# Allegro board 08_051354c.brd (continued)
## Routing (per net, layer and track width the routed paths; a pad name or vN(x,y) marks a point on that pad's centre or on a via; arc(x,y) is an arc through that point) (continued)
UNNAMED_5_ADP5023_I567_AVIN: length 18.1
  L8_SIG w0.508: v1(13.97,3.05) 14.22,3.05 15.01,3.84 15.01,4.76 14.35,5.42 14.35,9.86 v2(16.56,12.06)
  BOTTOM w0.133: R97.1 v1(13.97,3.05) ; v2(16.56,12.06) 16.65,12.16 U3.12
  BOTTOM w0.254: v1(19.43,17.14) 19.21,16.92 U3.22
  BOTTOM w0.305: U3.17 16.34,14.91 16,15.24 ; U3.7 v2(20.87,12.16) ; U3.3 21.92,14.41 ; 16.06,14.41 U3.16
  vias: v2(15.49,14.61) v2(15.75,15.88) v2(22.43,17.9) v2(23.24,17.95)
UNNAMED_5_ADP5023_I567_FB1: length 4.7
  TOP w0.305: v1(17.57,10.92) 17.57,10.11 17.7,9.98 R30.1 R23.1
  BOTTOM w0.133: U3.11 18.21,11.55 v1(17.57,10.92)
UNNAMED_5_ADP5023_I567_FB2: length 7.6
  TOP w0.305: v1(20.16,8.58) 20.16,10 20.83,10.67 v1(20.83,11.23)
  BOTTOM w0.133: R21.1 R20.1 19.35,8.17 19.75,8.58 v1(20.16,8.58)
  BOTTOM w0.305: U3.8 19.71,11.58 20.06,11.23 v1(20.83,11.23)
UNNAMED_5_ADP5023_I567_FB3: length 6.6
  TOP w0.133: v1(17.45,17.14) 17.09,16.79 14.38,16.79 14.01,17.15 R19.1 R18.2
  BOTTOM w0.254: v1(17.45,17.14) 17.71,16.88 U3.19
UNNAMED_5_ADP5023_I567_MODE: length 13.7
  L8_SIG w0.203: v1(16.38,10.67) 15.11,9.4 15.11,5.59 v1(17.65,3.05)
  BOTTOM w0.133: R97.2 v1(17.65,3.05) ; v1(16.38,10.67) 15.88,11.18 15.88,12.4 16.38,12.91 U3.13
UNNAMED_5_ADP5023_I567_SW1: length 4.5
  BOTTOM w0.254: U3.15 15.81,13.91 15.75,13.97 15.24,13.97 15.15,13.97 15.1,13.92 12.53,13.92
UNNAMED_5_ADP5023_I567_SW2: length 3.6
  BOTTOM w0.254: U3.4 24.57,13.91
UNNAMED_5_ADP5023_I567_VOUT1: length 9.4
  TOP w0.508: R22.1 20.06,7.4 18.95,8.51 v1(18.63,8.51) 18.02,7.91 R30.2
  BOTTOM w0.254: 18.71,10.83 U3.10 ; 18.71,10.83 18.72,10.84 ; 18.71,10.83 18.41,10.54
UNNAMED_5_ADP5023_I567_VOUT2: length 12.7
  BOTTOM w0.305: U3.9 19.21,10.05 19.6,9.65 ; 26.44,10.18 26.44,10.27 C47.1 26.5,10.25 26.44,10.18 ; 26.44,10.18 26.44,9.14 26.14,8.84 23.83,8.84 21.47,6.48 R21.2 20.49,5.34 R32.1
UNNAMED_5_ADP5023_I567_VOUT3: length 1.2
  BOTTOM w0.254: U3.20 18.21,17.35
  vias: v1(17.11,17.97) v1(17.79,17.97)
UNNAMED_5_ADP5071_I420_COMP1: length 2.1
  TOP w0.133: R50.1 26.67,24.51 25.89,23.73 U10.6
UNNAMED_5_ADP5071_I420_COMP2: length 1.9
  TOP w0.133: R51.1 23.29,24.61 23.89,24 U10.10
UNNAMED_5_ADP5071_I420_EN1: length 15.1
  TOP w0.133: R92.1 33.27,25.65 30.73,25.65 28.96,27.43 26.92,27.43 26.4,27.95 25.57,27.95 25.02,27.41 25.02,24.77 25.39,24.39 U10.7
UNNAMED_5_ADP5071_I420_EN2: length 20.8
  TOP w0.133: R85.2 36.83,25.26 36.83,26.54 36.32,27.05 33.07,27.05 30.78,29.34 27.12,29.34 26.53,28.75 25.45,28.75 24.39,27.69 U10.9
UNNAMED_5_ADP5071_I420_FB1: length 4.6
  TOP w0.133: 29.89,23.38 29.88,23.39 28.69,23.39 27.6,22.31 U10.5 ; 29.89,23.38 R48.1 ; 29.89,23.38 R52.1
UNNAMED_5_ADP5071_I420_FB2: length 6.2
  TOP w0.305: R49.1 R46.2 20.23,24.9 21.13,24.01 21.13,22.73 21.55,22.31 U10.11
UNNAMED_5_ADP5071_I420_INBK: length 4.4
  TOP w0.305: U10.1 30.28,20.31 30.84,20.87 L9.1
UNNAMED_5_ADP5071_I420_PVIN1: length 10.8
  TOP w0.305: U10.15 22.71,20.31 22.7,20.31 21.91,20.31 20.42,18.82 20.42,16.89 20.68,16.64 21.21,16.64 ; U10.16 23.89,16.24 C41.1 ; U10.17 24.39,18.04
UNNAMED_5_ADP5071_I420_SW2: length 1.5
  TOP w0.305: U10.18 24.89,17.83
UNNAMED_5_ADP5071_I420_VREF: length 6.3
  TOP w0.305: U10.12 21.12,21.81 20.29,22.63 C43.1 20.15,24.07 19.23,24.99 R46.1
UNNAMED_5_ADP5071_I420_VREG: length 3
  TOP w0.305: U10.14 21.14,20.81 20.37,20.04 C66.1
UNNAMED_5_ADP7112_I458_EN: length 8.7
  TOP w0.133: U12.C1 102.12,10.61 v1(102.12,11.18) 102.12,13.35 102.36,13.59 105.16,13.59 105.66,14.09 R111.2
  BOTTOM w0.133: v1(102.12,11.18) 102.13,11.18 R38.1
UNNAMED_5_ADP7112_I458_SENSE: length 5.4
  TOP w0.133: 100.98,10.24 101.18,10.03 U12.B2
  TOP w0.305: R57.1 97.51,9.84 R58.1 97.97,10.29 100.93,10.29 100.98,10.24
UNNAMED_5_ADP7112_I458_SS: length 2.7
  TOP w0.133: v1(103.52,10.41) 102.88,10.41 102.5,10.03 U12.B1
  BOTTOM w0.133: C80.1 103.78,10.68 v1(103.52,10.41)
UNNAMED_5_ADP7112_I458_VIN: length 4.1
  TOP w0.133: U12.A1 102.38,9.2
  TOP w0.508: R56.2 106.06,8.09 ; 104.03,7.73 C79.1 102.67,8.89
UNNAMED_5_ADP7112_I458_VOUT: length 6.1
  TOP w0.133: U12.A2 101.18,9.27
  TOP w0.508: R59.1 97.51,7.82 R58.2 97.58,8.89 C81.1 ; C81.1 99.45,7.75 ; C81.1 100.81,8.89
UNNAMED_5_CAP_I499_N1: length 20.8
  TOP w0.305: R49.2 19.23,27.55 v1(19.24,27.56)
  L3_SIG w0.305: v1(19.24,27.56) 19.24,25.56 20.24,24.57 20.24,9.57 21.05,8.76 v1(21.46,8.76)
UNNAMED_5_CAP_I500_N1: length 15.4
  TOP w0.133: R52.2 v1(31.77,23.37)
  TOP w0.508: C78.1 32.51,13.21 33.02,12.7 v1(33.02,11.69)
  L3_SIG w0.305: v1(31.77,23.37) 31.77,12.94 v1(33.02,11.69)
UNNAMED_5_CAP_I511_N1: length 16.4
  BOTTOM w0.508: 8.42,28.3 C42.1 ; C42.1 9.86,27.35 ; C42.1 11.29,28.3 ; C42.1 9.86,29.25 ; R100.2 8.07,32.14 ; R100.2 7.27,31.24 ; R100.2 7.27,33.04 ; E2.1 7.27,30.83 ; E2.1 7.27,28.57 ; E2.1 8.27,29.7 ; S2.2 14.15,26.54 ; S2.2 12.7,27.99 ; S2.2 11.25,26.54 ; S2.2 12.7,25.09
UNNAMED_5_CAP_I516_N1: length 1.1
  TOP w0.133: R50.2 C72.1
UNNAMED_5_CAP_I517_N1: length 1.1
  TOP w0.305: R51.2 C74.1
UNNAMED_5_CAP_I691_N1: length 2
  BOTTOM w0.279: U2.23 24.1,35.14 C38.1
UNNAMED_5_CAP_I700_N2: length 1.9
  BOTTOM w0.279: U2.28 26.6,35.01 C35.2
UNNAMED_5_CAP_I722_N2: length 1.4
  BOTTOM w0.254: R13.1 C91.2
UNNAMED_5_CN4PV6_I401_N1: length 21.8
  TOP w0.508: P31.1B 4.67,5.38 ; P31.1B 3.06,3.58 ; P31.1B 3.06,7.18 ; P31.1A 3.06,13.28 ; P31.1A 4.67,11.48 ; P31.1A 3.06,9.68 ; D1.C 7.23,19.11 ; D1.C 7.23,16.13 ; D1.C 5.94,17.62 ; D1.C 8.53,17.62 ; S2.1 14.15,21.84 ; S2.1 12.7,20.4 ; S2.1 12.7,23.29 ; S2.1 11.25,21.84
UNNAMED_5_DIOLED_I652_P: length 5.7
  TOP w0.508: DS1.A 7.64,34.66 v1(6.77,34.66)
  BOTTOM w0.508: v1(6.77,34.66) 5.57,33.46 R100.1
UNNAMED_5_DIOLED_I662_P: length 2.6
  TOP w0.508: v1(7.62,39.24) DS2.A
  BOTTOM w0.508: v1(7.62,39.24) R104.2
UNNAMED_5_DIOLED_I714_P: length 2.6
  TOP w0.508: DS3.A v1(7.61,42.42)
  BOTTOM w0.508: R108.1 v1(7.61,42.42)
UNNAMED_5_LINLTC3119_I686_RT: length 2.7
  BOTTOM w0.254: R14.1 22.73,26.8 24.1,28.16 U2.14
UNNAMED_5_LINLTC3119_I686_VC: length 2.1
  BOTTOM w0.254: U2.10 26.1,27.95 26.8,27.25 R13.2
UNNAMED_5_RES_I689_N2: length 1.6
  BOTTOM w0.133: R115.1 19.56,23.11 R15.2
UNNAMED_6_CAP_I286_N1: length 55.6
  TOP w0.305: v1(43.94,6.48) 43.18,5.71 C85.1 41.85,4.58 41.24,3.98 S4.1
  L8_SIG w0.203: v1(65.55,39.88) 65.55,39.39 64.52,38.35 56.31,38.35 51.94,33.99 51.94,21.44 50.25,19.75 48.2,19.75 44.52,16.07 44.52,14.36 44.55,14.34 44.55,7.08 v1(43.94,6.48)
  BOTTOM w0.133: P4.28 v1(65.55,39.88)
UNNAMED_6_CAP_I292_N1: length 66.2
  TOP w0.305: v1(36.96,5.71) C84.1 38.04,4.58 38.64,3.98 S3.2
  L8_SIG w0.203: v1(36.96,5.71) 36.96,6.73 37.92,7.7 42.27,7.7 43.18,6.78 43.18,6.32 43.79,5.71 44.32,5.71 45.06,6.45 45.06,13.86 45.9,14.7 45.9,16.45 48.17,18.72 50.88,18.72 52.65,20.5 52.65,33.93 56.44,37.72 66.03,37.72 v1(67.55,39.24)
  BOTTOM w0.133: P4.29 v1(67.55,39.24)
UNNAMED_6_CN30PV2_I274_N13: length 6.8
  TOP w0.133: v1(48.4,26.68) 48.09,27 P1.13
  BOTTOM w0.133: R98.2 50.07,29.59 48.77,28.28 48.77,27.05 v1(48.4,26.68)
UNNAMED_6_CN30PV2_I274_N14: length 7.6
  TOP w0.133: P1.14 47.95,28 v1(49.28,26.67)
  BOTTOM w0.133: v1(49.28,26.67) 49.15,26.8 49.15,28.12 49.98,28.96 50.93,28.96 R109.2
UNNAMED_6_CN60PODDEVEN_I272_N5: length 2.5
  TOP w0.133: R113.2 53.43,3.8 v1(53.89,4.26)
  BOTTOM w0.133: v1(53.89,4.26) P3.9
UNNAMED_6_DIOLED_I296_N: length 54.2
  TOP w0.133: DS5.C v1(42.58,6.48) ; Q2.3 v1(17.03,36.96)
  L8_SIG w0.203: v1(17.03,36.96) 17.03,36.91 15.81,35.69 15.81,30.67 16.76,29.72 16.76,26.94 24.08,19.62 24.08,15.24 25.4,13.92 25.4,10.19 30.76,4.83 37.21,4.83 37.85,5.46 37.85,6.6 38.35,7.11 41.95,7.11 v1(42.58,6.48)
UNNAMED_6_DIOLED_I296_P: length 1.7
  TOP w0.305: DS5.A 40.98,9.09 R75.2
UNNAMED_6_DIOLED_I301_N: length 54.2
  TOP w0.133: Q2.6 14.88,39.56 v1(14.82,39.5) ; DS4.C v1(38.9,6.44)
  L8_SIG w0.203: v1(14.82,39.5) 14.77,39.45 14.77,39.12 14.78,39.1 14.78,27.69 21.77,20.7 21.77,16.43 24.77,13.44 24.77,9.93 31.14,3.56 31.6,3.56 32.11,4.06 37.47,4.06 38.9,5.5 v1(38.9,6.44)
UNNAMED_6_DIOLED_I301_P: length 1.7
  TOP w0.305: R37.2 37.3,9.09 DS4.A
UNNAMED_6_RES_I283_N2: length 2.1
  TOP w0.508: S4.2 47.14,2.42 R80.2
UNNAMED_6_RES_I294_N2: length 2.1
  TOP w0.508: S3.1 32.74,2.42 R77.2
UNNAMED_6_RES_I297_N2: length 2
  TOP w0.133: R79.2 15.66,41.11 16.38,40.39 Q2.5
UNNAMED_6_RES_I302_N2: length 2.2
  TOP w0.133: Q2.2 16.38,36.66 R78.2
UNNAMED_7_ADA4800_I153_IN: length 13.2
  TOP w0.133: U1.21 99.73,20.56 102.28,23.11 109.73,23.11 109.86,22.98 A1.1
UNNAMED_7_ADA4800_I153_OUT: length 1.6
  TOP w0.254: R76.1 109.48,21.71 109.75,21.98 A1.3
UNNAMED_7_CAP_I99_N1: length 6.8
  BOTTOM w0.133: Q1.1 109.58,26.02 109.73,26.16 109.73,26.54 109.56,26.72 Q1.3 108.82,26.72 108.38,27.15 D5.A 107.77,27.76 108.62,28.61 C30.1 R27.1
UNNAMED_7_CAP_I107_N1: length 3.2
  BOTTOM w0.133: R7.2 C18.1 108.4,25.85 108.91,26.36 109.28,26.36 109.28,26.37 Q1.2
UNNAMED_7_CAP_I123_N2: length 2.8
  TOP w0.254: 113.11,22.2 113.11,21.62 112.56,21.07 R33.2 ; A1.5 113.03,22.48
UNNAMED_7_CAP_I131_N1: length 2.2
  TOP w0.254: U1.30 99.26,26.78
  TOP w0.381: U1.30 v2(98.24,27.94)
  vias: v2(99.19,27.94)
UNNAMED_7_CAP_I133_N1: length 0.5
  BOTTOM w0.133: R69.2 C73.1
UNNAMED_7_CAP_I133_N2: length 5.2
  TOP w0.133: v1(97.2,21.86) U1.23
  BOTTOM w0.133: C73.2 96.38,25.08 97.2,24.26 v1(97.2,21.86)
UNNAMED_7_CAP_I142_N1: length 2
  TOP w0.406: v1(96.57,21.34) 97.11,20.8 U1.19
UNNAMED_7_CAP_I150_N1: length 2.2
  TOP w0.133: C21.1 109.95,20.01 109.59,20.01 R76.2
UNNAMED_7_CAP_I151_N2: length 3.7
  TOP w0.133: C29.2 R31.1 113.47,23.63 112.82,22.98 A1.6
UNNAMED_7_CAP_I152_N1: length 3.1
  TOP w0.133: A1.4 112.21,21.73 111.55,21.08 111.55,20.45 R33.1 C65.1
UNNAMED_7_ICFAN3121_I89_EN: length 11.3
  BOTTOM w0.133: R118.1 95.5,12.18 98.11,14.8 102.35,14.8 102.66,15.11 102.66,15.78 102.46,15.98 U6.3
UNNAMED_7_ICFAN3121_I89_IN: length 4.2
  BOTTOM w0.133: U6.2 102.54,16.63 103.04,16.13 103.04,14.68 102.52,14.16 R5.2
UNNAMED_7_MN34906BL_I91_HL: length 7.1
  TOP w0.133: U1.17 v1(95.81,20.7)
  BOTTOM w0.133: R66.2 91.33,22.01 92.65,20.7 v1(95.81,20.7)
UNNAMED_7_RES_I93_N2: length 1.4
  BOTTOM w0.133: R26.2 111.3,26.02 Q1.6 Q1.5
UNNAMED_10_ADDI9036_I362_AUXINA: length 23.8
  TOP w0.133: C57.2 R73.2 70.65,32.9 RT1.2 ; RT1.2 69.06,32.62 R72.1 ; RT1.2 70.37,31.61 70.74,31.24 v1(71.37,31.24)
  L2_GND w0.14: v5(74.4,22.91) 74.9,23.41 v4(74.9,23.41)
  L3_SIG w0.102: v5(74.4,22.91) 73.79,23.52 71.05,23.52 70.67,23.9 67.55,23.9 67.23,24.22 67.23,27.7 70.76,31.24 v1(71.37,31.24)
UNNAMED_10_ADDI9036_I362_DNC3: length 10.8
  TOP w0.133: v4(73.07,18.71) 73.07,16.3 70.36,13.59 69.5,13.59 R89.1
  L2_GND w0.14: v4(73.07,18.71) 73.07,18.97 74.9,20.8 v4(74.9,21.41)
UNNAMED_10_ADDI9036_I362_DNC4: length 32.9
  L3_SIG w0.102: v1(68.24,20.32) 68.24,20.02 69.1,19.16 70.03,19.16 71.02,20.16 72.81,20.16 74.57,21.91 v5(75.4,21.91)
  L8_SIG w0.203: v1(68.24,20.32) 68.24,21.95 67.23,22.96 67.23,25.99 v1(64.52,28.7)
  BOTTOM w0.133: R88.1 75.44,26.96 75.44,27.69 73.53,29.59 71.88,29.59 70.74,28.45 64.77,28.45 v1(64.52,28.7)
UNNAMED_10_ADDI9036_I362_I2CSCL: length 20.2
  L3_SIG w0.102: v1(70.51,27.74) 70.79,28.02 73.17,28.02 73.76,27.42 74.84,27.42 75.74,26.52 75.74,24.23 75.56,24.05 75.56,23.42 75.9,23.08 v5(75.9,22.41)
  BOTTOM w0.133: v1(70.51,27.74) 70.51,24.31 73.19,21.63 R28.2 R41.2
UNNAMED_10_ADDI9036_I362_I2CSDA: length 7.9
  L3_SIG w0.102: 74.85,26.34 74.85,26.42 v3(74.83,26.44)
  L3_SIG w0.122: 74.85,26.34 74.85,25.63 75.25,25.24 75.25,23.2 75.4,23.05 v5(75.4,22.41)
  BOTTOM w0.133: R6.2 R3.2 75.34,25.06 74.83,25.58 v3(74.83,26.44)
UNNAMED_10_ADDI9036_I362_MTEST: length 8
  L2_GND w0.14: v4(77.4,21.41) 78.55,20.26 78.55,20.07
  L2_GND w0.203: 78.55,20.07 78.55,19.62 v1(80.17,18.01)
  BOTTOM w0.133: R2.2 80.01,20.93 80.01,18.67 80.17,18.51 v1(80.17,18.01)
UNNAMED_10_FERRITE_I381_N1: length 5
  TOP w0.133: Y1.4 63.65,26.95 R1.2 64.3,28.22 C5.1 66.41,27.21 E1.1
UNNAMED_10_ICAT24CM01_I285_A2: length 3.7
  BOTTOM w0.133: U5.3 45.42,16.81 R47.1 R54.2
UNNAMED_10_ICAT24CM01_I285_WP: length 4.1
  BOTTOM w0.133: R60.2 R55.1 46.07,26.75 U5.7
UNNAMED_10_RES_I124_N1: length 1.6
  TOP w0.133: R1.1 62.65,26.95 Y1.1
UNNAMED_10_RES_I290_N1: length 3.5
  BOTTOM w0.133: R63.2 R62.1 46.07,16.69 U5.2
UNNAMED_10_RES_I374_N1: length 1.5
  TOP w0.133: Y1.3 63.87,23.94 63.86,23.94 R110.1
UNNAMED_12_ADT7410_I215_A0: length 4.4
  TOP w0.133: U13.3 91.07,10.54 R106.2 91.33,10.54 v1(92.22,10.54)
  BOTTOM w0.133: R106.2 91.33,10.54 v1(92.22,10.54)
UNNAMED_12_ADT7410_I215_A1: length 4.4
  TOP w0.133: U13.4 91.07,11.81 R103.2 91.33,11.81 v1(92.22,11.81)
  BOTTOM w0.133: R103.2 91.33,11.81 v1(92.22,11.81)
UNNAMED_12_ICFSA642_I1_OEN: length 2.4
  BOTTOM w0.133: U7.8 74.65,10.26 74.92,9.99 75.92,9.99 76.04,10.11 R90.2
UNNAMED_12_ICFSA642_I193_OEN: length 2.3
  BOTTOM w0.133: U11.8 53.49,12.39 53.67,12.57 53.67,13.7 R84.1
UNNAMED_12_ICPCA9517A_I144_EN: length 2.7
  TOP w0.133: U8.5 87.86,38.9 88.66,38.1 R101.1
UNNAMED_12_ICPCA9517A_I227_EN: length 3.6
  BOTTOM w0.133: U9.5 75.79,33.23 76.34,33.78 R24.2
UNNAMED_12_ICPCA9517A_I229_EN: length 2.2
  BOTTOM w0.133: R4.2 52.45,24.9 52.45,24.76 52.85,24.37 U14.5
UNNAMED_12_RES_I54_N1: length 2.9
  TOP w0.133: S1.1 2.92,41.27 3.13,41.49 R91.1
UNNAMED_12_RES_I55_N2: length 2.1
  TOP w0.133: R36.2 2.29,37.47 S1.3
VL: length 0.9
  TOP w0.635: R10.1 v1(85.34,28.45)
  vias: v2(27.14,3.11) v2(27.52,2.35) v2(28.32,3.08) v2(28.92,2.35) v2(29.43,3.11) v2(102.87,36.32) v2(102.87,35.43)
VL_AFE: length 7.1
  TOP w0.133: U4.K11 77.4,25.71 77.6,25.91
  TOP w0.305: C27.1 79.71,26.53 79.52,26.34 78.03,26.34 77.6,25.91
  TOP w0.508: C27.1 81.36,26.53 C20.2 82.04,27.21 82.04,27.77 R10.2
VLD: length 19.5
  TOP w0.254: P21.24 59.46,24.67 ; P21.10 59.46,28.17 ; P21.6 59.46,29.17 ; P21.18 59.46,26.17 ; P21.14 59.46,27.17 ; P21.12 59.46,27.67 ; P21.20 59.46,25.67 ; P21.16 59.46,26.67 ; P21.2 59.46,30.18 ; P21.8 59.46,28.67 ; P21.4 59.46,29.67 ; P21.22 59.46,25.17
  BOTTOM w0.279: R108.2 v1(10.63,41.53)
  vias: v1(59.56,30.1) v1(59.56,28.57) v1(59.56,27.81) v1(59.56,27.05) v1(59.56,26.29) v1(59.65,29.34) v1(59.75,25.07) v1(60.24,27.12) v1(60.33,29.21) v2(18.54,38.99) v2(18.54,37.97) v2(19.81,38.99) v2(19.81,37.97) v2(37.47,34.92) v2(38.61,34.92) v2(39.75,34.92) v2(40.77,34.92) v2(40.77,33.91) v2(40.77,32.89) v2(41.91,34.92) v2(41.91,33.91) v2(41.91,32.89)
VSUB: length 6.5
  TOP w0.508: 106.69,15.1 R111.1 v2(105.66,15.09) ; v2(106.06,11.56) R56.1
  BOTTOM w0.305: U6.8 98.49,17.28 98.07,17.7 v2(98.07,17.89)
  BOTTOM w0.508: v1(96.9,11.81) 96.9,10.43 96.39,9.92 R117.1
  vias: v2(29.72,8.13) v2(29.72,6.86) v2(30.61,8.13) v2(30.61,6.86) v2(104.52,14.35) v2(104.57,17.68) v2(105.58,20.73) v2(105.58,19.71) v2(105.58,18.69) v2(105.58,17.68) v2(105.58,16.66)

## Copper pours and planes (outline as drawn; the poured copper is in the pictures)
5V_LD on TOP: 50.16,20.83 50.16,23.88 50.85,23.88 50.85,23.8 52.18,23.8 52.31,23.67 52.18,23.54 50.85,23.54 50.85,23.3 52.18,23.3 52.31,23.17 52.18,23.04 50.85,23.04 50.85,22.8 52.18,22.8 52.31,22.67 52.18,22.54 50.85,22.54 50.85,22.3 52.18,22.3 52.31,22.17 52.18,22.04 50.85,22.04 50.85,21.8 52.18,21.8 52.31,21.67 52.18,21.54 50.85,21.54 50.85,21.3 52.18,21.3 52.31,21.17 52.18,21.04 50.85,21.04 50.85,20.79 52.18,20.79 52.31,20.67 52.18,20.54 50.85,20.54 50.85,20.45 50.55,20.45
5V_LD on BOTTOM: 7.46,23.69 7.11,23.37 7.11,21.34 7.33,21.15 9.49,21.15 10,21.66 10,23.43 9.74,23.69
5V_LD on BOTTOM: 16.51,30.48 21.97,30.48 22.38,30.89 23.57,30.89 23.83,31.14 23.83,31.57 23.71,31.69 22.16,31.69 20.32,33.53 20.32,34.42 20.07,34.67 16.51,34.67 16.26,34.42 16.26,30.73
5V_LD on L5_PWR: 1.27,34.35 26.41,34.35 28,32.76 28,30.1 28.03,29.98 28.1,29.87 29.24,28.73 29.34,28.66 29.46,28.64 51.18,28.64 52.01,27.81 52.01,20.58 51.43,20 21.21,20 20.51,20.71 20.51,23.5 20.49,23.62 20.42,23.72 18.89,25.24 18.79,25.31 18.67,25.34 14.22,25.34 14.1,25.31 14,25.24 12.22,23.47 12.15,23.36 12.13,23.24 12.13,20.2 9.01,17.08 1.27,17.08
5VCC on TOP: 21.81,17.85 20.92,17.85 20.92,18.74 22.06,19.88 23.33,19.88 23.46,19.75 23.46,18.74 23.2,18.35 21.93,18.35 21.81,18.23
5VCC on BOTTOM: 6.17,28.91 6.19,28.9 6.19,30.93 5.93,31.18 3.52,31.18 3.27,30.93 3.27,29.15 2.88,28.77 1.61,28.77 1.36,28.51 1.36,26.48 1.61,26.23 3.65,26.23 4.03,26.61 5.81,26.61 5.93,26.74 5.93,28.65
5VCC on BOTTOM: 26.25,20.01 26.38,19.88 26.38,18.74 26.25,18.61 23.46,18.61 23.33,18.48 22.32,18.48 22.19,18.61 22.19,19.88 22.32,20.01
5VCC on L6_PWR: 1.27,32.83 13.2,32.83 13.65,32.38 13.65,27.69 13.68,27.56 13.75,27.46 15.9,25.3 16.01,25.23 16.13,25.21 30.09,25.21 31.78,23.52 31.88,23.46 32,23.43 40.38,23.43 40.83,22.98 40.83,14.35 40.85,14.23 40.92,14.13 42.99,12.06 42.99,6.74 41.91,5.65 30.73,5.65 30.61,5.63 30.51,5.56 29.49,4.54 29.42,4.44 29.4,4.32 29.4,1.27 1.27,1.27 ; 1 cut-out
9VDD on TOP: 94.95,7.29 96.88,7.29 96.88,8.18 95.02,8.18 94.23,8.97 93.05,8.97 93.05,7.45 94.78,7.45
9VDD on L6_PWR: 88.65,27.88 125.59,27.88 125.59,7.27 92.52,7.27 92.52,22.1 92.5,22.22 92.43,22.32 91.28,23.47 91.18,23.53 91.06,23.56 86.11,23.56 85.79,23.88 85.79,25.01
GND on TOP: 1.27,43.73 125.59,43.73 125.59,7.27 92.81,7.27 92.81,10.59 89.53,10.59 89.53,12.38 84.77,12.38 84.77,7.27 77.73,7.27 77.73,1.27 1.27,1.27 ; 55 cut-outs
GND on BOTTOM: 1.27,43.71 125.59,43.71 125.59,7.29 77.73,7.29 77.73,1.27 1.27,1.27 1.27,25.68 1.45,25.86 3.63,25.86 3.89,25.6 3.89,23.9 4.17,23.62 4.19,23.65 6.55,23.65 6.73,23.47 6.73,20.85 7.06,20.52 9.73,20.52 10.62,21.41 10.62,23.77 10.79,23.95 14.43,23.95 15.19,24.71 15.19,29.34 12.09,32.44 8.99,32.44 8.99,33.48 8.51,33.96 1.85,33.96 1.27,33.38 ; 12 cut-outs
GND on BOTTOM: 21.77,13.54 23.8,13.54 24.13,13.21 24.13,11.94 23.75,11.56 22.86,11.56 22.23,10.92 21.46,10.92 21.34,11.05 21.34,12.42 21.77,12.85
GND on BOTTOM: 12.75,13.59 16.18,13.59 16.18,13.23 16.07,13.23 15.92,13.08 15.92,12.95 13.89,10.92 13.08,10.92 12.49,11.51 12.49,13.34
GND on L2_GND: 77.73,7.27 77.73,1.27 1.27,1.27 1.27,43.73 125.59,43.73 125.59,7.27 ; 2 cut-outs
GND on L3_SIG: 1.27,43.73 125.59,43.73 125.59,7.27 77.73,7.27 77.73,1.27 1.27,1.27 ; 18 cut-outs
GND on L4_GND, L9_GND: 77.73,1.27 1.27,1.27 1.27,43.73 125.59,43.73 125.59,7.27 77.73,7.27
GND on L7_GND: 77.73,7.29 77.73,1.27 1.27,1.27 1.27,43.71 125.59,43.71 125.59,7.29
GND on L8_SIG: 77.73,7.27 77.73,1.27 1.27,1.27 1.27,43.73 125.59,43.73 125.59,7.27 ; 5 cut-outs
VCC on BOTTOM: 42.55,27.3 42.55,24.64 42.16,24.26 37.34,24.26 37.08,24.51 37.08,26.04 37.34,26.29 39.88,26.29 40.39,26.8 40.39,27.3 40.51,27.43 42.42,27.43
VCC on L6_PWR: 14.74,32.83 40.25,32.83 40.83,32.25 40.83,24.52 40.38,24.07 32.14,24.07 30.45,25.75 30.35,25.82 30.23,25.84 16.26,25.84 14.29,27.82 14.29,32.38
1P8VDD on TOP: 16.85,24.32 15.46,24.32 15.2,24.07 15.2,22.55 15.46,22.29 16.85,22.29 17.11,22.55 17.11,24.07
1P8VDD on L5_PWR: 63.82,43.73 78.93,43.73 78.93,28.83 78.95,28.71 79.02,28.6 80.29,27.33 80.4,27.27 80.52,27.24 91.82,27.24 93.03,26.03 93.03,16.51 92.45,15.94 57.53,15.94 57.41,15.91 57.31,15.85 55.88,14.41 32.38,14.41 32.26,14.39 32.16,14.32 28.1,10.26 28.03,10.15 28,10.03 28,6.1 25.68,3.78 25.61,3.68 25.59,3.56 25.59,1.27 1.27,1.27 1.27,16.45 9.14,16.45 9.27,16.47 9.37,16.54 12.67,19.84 12.74,19.94 12.76,20.07 12.76,23.11 14.36,24.7 18.54,24.7 19.88,23.36 19.88,19.82 17.05,16.99 16.98,16.89 16.95,16.76 16.95,12.06 16.98,11.94 17.05,11.84 18.06,10.82 18.17,10.76 18.29,10.73 23.62,10.73 23.74,10.76 23.85,10.82 25.12,12.09 25.19,12.2 25.21,12.32 25.21,18.79 25.79,19.37 51.56,19.37 51.68,19.39 51.79,19.46 52.55,20.22 52.62,20.33 52.64,20.45 52.64,23.11 53.22,23.69 62.74,23.69 62.86,23.71 62.96,23.78 63.72,24.54 63.79,24.64 63.82,24.77
2P1VDD on BOTTOM: 18.59,16.84 18.59,19.56 18.72,19.68 20.11,19.68 20.27,19.53 20.27,17.83 20.07,17.63 19.2,17.63 18.84,17.27 18.84,16.84
2P1VDD on BOTTOM: 17.57,3.68 17.32,3.94 17.32,5.59 17.45,5.71 19.22,5.71 19.48,5.46 19.48,4.19 18.97,3.68
2P1VDD on L8_SIG: 17.56,3.78 20.34,3.78 20.72,4.17 20.72,18.18 20.42,18.48 18.74,18.48 18.5,18.23 18.5,17.63 17.16,16.29 17.16,4.18
3P3VDD on L6_PWR: 74.43,35.5 75.94,35.5 76.39,35.05 76.39,29.97 76.41,29.85 76.48,29.75 77.37,28.86 77.48,28.79 77.6,28.77 80.39,28.77 80.58,28.57 80.58,28.2 77.5,25.12 77.43,25.01 77.41,24.89 77.41,21.09 74.67,18.35 72.39,18.35 72.27,18.33 72.17,18.26 70.61,16.7 67.06,16.7 66.48,17.28 66.48,27.55
3P5VDD on L6_PWR: outline of 88 points within 1.27,1.27 125.59,43.73
IOVDD on L6_PWR: 72.52,41.47 79.88,41.47 80.33,41.02 80.33,36.96 79.5,36.13 77.34,36.13 77.31,36.13 77.28,36.13 77.25,36.13 77.22,36.13 74.3,36.13 74.17,36.11 74.07,36.04 65.94,27.91 65.87,27.81 65.85,27.69 65.85,17.14 65.87,17.02 65.94,16.92 66.7,16.16 66.81,16.09 66.93,16.07 70.74,16.07 70.86,16.09 70.96,16.16 72.52,17.72 74.8,17.72 74.92,17.74 75.03,17.81 77.86,20.64 79.88,20.64 82.23,18.28 82.23,13.47 80.51,11.75 59.44,11.75 58.39,12.8 58.29,12.87 58.17,12.89 52.96,12.89 52.84,12.87 52.73,12.8 51.46,11.53 51.4,11.42 51.37,11.3 51.37,1.27 30.04,1.27 30.04,4.19 30.87,5.02 42.04,5.02 42.16,5.04 42.26,5.11 43.53,6.38 43.6,6.48 43.62,6.6 43.62,12.19 43.6,12.31 43.53,12.42 41.47,14.48 41.47,32.25 42.01,32.8 42.04,32.83 45.33,32.83 48.2,29.97 48.2,27.94 48.22,27.82 48.29,27.72 49.05,26.95 49.15,26.88 49.28,26.86 52.83,26.86 52.95,26.88 53.06,26.95 54.07,27.97 54.14,28.07 54.17,28.19 54.17,29.84 55.25,30.92 61.85,30.92 61.97,30.95 62.07,31.02
PVOUT on BOTTOM: 26.95,31.62 28.6,31.62 30.61,33.63 38.07,33.63 38.07,31.85 42.93,31.85 43.18,31.6 43.18,30.48 43,30.3 30.56,30.3 30.12,30.73 28.7,30.73 28.5,30.94 26.95,30.94
SW1 on BOTTOM: 22.99,32.08 22.58,32.08 21.34,33.32 21.34,41.78 21.84,42.29 24,42.29 24,37.08 22.86,35.94 22.86,32.51 22.99,32.38
SW2 on BOTTOM: 27.69,32.03 28.45,32.03 29.62,33.2 29.62,41.63 28.96,42.29 26.92,42.29 26.92,37.08 27.94,36.07 27.94,32.38 27.69,32.13
UNNAMED_5_ADP5023_I567_AVIN on BOTTOM: 16.13,15.11 16.13,16.05 15.29,16.89 14.27,16.89 14.14,16.76 14.14,16.13 14.27,16 15.04,16 15.93,15.11
UNNAMED_5_ADP5023_I567_AVIN on BOTTOM: 16.21,14.56 16.1,14.56 14.91,15.75 13,15.75 12.87,15.62 12.87,14.48 13.13,14.22 16.21,14.22
UNNAMED_5_ADP5023_I567_AVIN on BOTTOM: 22.05,14.22 22.02,14.25 21.79,14.25 21.79,14.94 22.19,15.33 22.19,18.1 22.32,18.23 23.59,18.23 24.22,17.59 27.14,17.59 27.27,17.47 27.27,15.81 27.14,15.69 24.6,15.69 24.36,15.42 24.34,15.42 24.09,15.18 24.09,14.22
UNNAMED_5_ADP5023_I567_AVIN on L5_PWR: 20.32,19.37 24,19.37 24.57,18.79 24.57,12.45 23.49,11.37 18.42,11.37 17.59,12.2 17.59,16.63
UNNAMED_5_ADP5023_I567_AVIN on L6_PWR: 20.07,18.48 23.74,18.48 24.19,18.03 24.19,12.45 23.36,11.62 15.88,11.62 14.92,12.58 14.92,16.38 15.63,17.08 18.54,17.08 18.66,17.11 18.77,17.17
UNNAMED_5_ADP5023_I567_SW1 on BOTTOM: 12.49,14.99 12.49,14.35 12.87,13.97 16.68,13.97 16.68,13.84 16.56,13.72 12.49,13.72 12.24,13.46 9.57,13.46 9.44,13.59 9.44,14.99 9.57,15.11 12.37,15.11
UNNAMED_5_ADP5023_I567_SW2 on BOTTOM: 24.35,13.78 24.26,13.78 24.26,14.04 24.35,14.04 24.6,14.29 24.6,14.93 24.73,15.05 27.27,15.05 27.4,14.93 27.4,13.66 27.27,13.53 24.6,13.53
UNNAMED_5_ADP5023_I567_VOUT1 on BOTTOM: 12.11,9.14 12.11,7.75 12.24,7.62 18.31,7.62 18.84,8.15 18.84,9.91 18.85,9.96 18.84,10.16 18.85,10.95 18.85,11.43 18.59,11.43 18.59,11.3 16.81,9.53 14.14,9.53 12.24,11.43 12.24,13.08 12.11,13.21 9.57,13.21 9.44,13.08 9.44,11.81
UNNAMED_5_ADP5023_I567_VOUT2 on BOTTOM: 19.08,11.43 19.08,10.01 19.77,9.34 27.78,9.34 27.9,9.46 27.9,12.89 27.78,13.15 24.98,13.15 24.81,12.95 24.81,11.43 24.56,11.18 23.16,11.18 22.53,10.54 20.14,10.54 19.25,11.43
UNNAMED_5_ADP5023_I567_VOUT3 on TOP: 16.98,17.59 18.25,17.59 18.38,17.72 18.38,18.48 18.25,18.61 17.62,18.61 17.11,19.12 17.11,21.78 16.98,21.91 15.33,21.91 15.2,21.78 15.2,20.51 15.46,20.26 15.71,20.26 15.84,20.13 15.84,18.61 15.46,18.23 14.7,18.23 14.7,17.47 14.95,17.21 16.6,17.21
UNNAMED_5_ADP5023_I567_VOUT3 on BOTTOM: 18.33,16.84 18.33,19.56 18.21,19.68 16.81,19.68 16.68,19.56 16.68,17.78 16.81,17.65 17.7,17.65 18.08,17.27 18.08,16.84
UNNAMED_5_ADP5071_I420_INBK on TOP: 27.84,20.45 28.16,20.77 28.16,21.66 28.54,22.04 32.98,22.04 33.24,21.78 33.24,20.13 32.98,19.88 27.99,19.88 27.69,20.2 27.69,20.41 27.72,20.45
UNNAMED_5_ADP5071_I420_PVIN1 on TOP: 23.75,18.41 24.51,18.41 24.51,17.4 24.35,17.24 24.35,14.42 21.05,14.42 20.92,14.54 20.92,17.47 21.05,17.59 21.68,17.59 21.87,17.4 23.37,17.4 23.75,17.78
UNNAMED_5_ADP5071_I420_SW1 on TOP: 25.76,18.97 25.76,19.68 25.81,19.74 27.43,19.74 28.09,19.08 33.09,19.08 33.57,19.56 36.88,19.56 37,19.43 37,17.53 36.88,17.4 28.4,17.4 27.05,18.75 25.98,18.75
UNNAMED_5_ADP5071_I420_SW2 on TOP: 26.51,13.02 26.51,9.85 26.25,9.59 24.35,9.59 23.71,10.23 22.32,10.23 22.19,10.35 22.19,13.66 22.44,13.91 24.22,13.91 24.73,14.42 24.73,18.48 25.24,18.48 25.24,14.29
UNNAMED_5_ADP7112_I458_VIN on TOP: 106.77,8.83 105.75,8.83 105.12,9.59 102.51,9.59 101.9,8.99 101.9,7.47 102.07,7.31 106.9,7.31 107.02,7.43 107.02,8.58
UNNAMED_5_ADP7112_I458_VOUT on TOP: 97.5,8.45 97.76,8.45 98.77,9.46 101.13,9.46 101.57,9.02 101.57,7.57 101.29,7.29 97.26,7.29 97.26,8.21
UNNAMED_5_CAP_I59_N2 on BOTTOM: 4.47,25.95 4.47,24.21 4.64,24.05 7.08,24.05 7.35,24.32 9.74,24.32 10,24.58 10,25.81 9.7,26.1 8.13,26.1 7.78,26.45 7.78,27.42 7.57,27.63 6.45,27.63 6.27,27.45 6.27,26.27 6.13,26.13 4.66,26.13
UNNAMED_5_CAP_I499_N1 on TOP: 21,9.4 23.67,9.4 24.05,9.14 24.05,4.57 23.29,3.81 23.29,2.29 22.02,2.29 20.7,3.6 20.7,9.1
UNNAMED_5_CAP_I500_N1 on TOP: 36.92,16.83 37.05,16.7 37.05,12.39 36.79,12.26 32.35,12.26 31.21,11.12 31.21,9.85 31.08,9.72 29.94,9.72 29.81,9.85 29.81,13.53 30.32,14.16 33.62,14.16 34.38,14.93 34.38,16.7 34.51,16.83
UNNAMED_5_CAP_I511_N1 on BOTTOM: 14.19,24.58 14.57,24.96 14.57,29.02 14.06,29.53 12.03,29.53 11.52,30.04 9.23,30.04 8.35,30.93 8.35,33.21 8.22,33.34 6.82,33.34 6.69,33.21 6.69,28.26 6.82,28.13 7.71,28.13 8.09,27.75 8.09,26.99 8.47,26.61 9.74,26.61 10.38,25.97 10.38,24.96 10.76,24.58
UNNAMED_5_CN4PV6_I401_N1 on TOP: 1.36,3.08 1.97,2.48 5.93,2.48 6.19,2.73 6.19,12.13 8.98,14.93 8.98,18.23 10.38,19.62 13.81,19.62 14.57,20.39 14.57,24.07 14.31,24.32 10.63,24.32 10.38,24.07 10.38,21.78 9.36,20.77 6.06,20.77 5.04,19.75 5.04,18.74 1.36,15.05
UNNAMED_5_FERRITE_I642_N2 on TOP: 25.65,3.17 25.65,2.41 25.4,2.16 23.88,2.16 23.62,2.41 23.62,3.17 23.88,3.43 25.4,3.43
UNNAMED_7_CAP_I123_N2 on TOP: 112.98,22.04 116.42,22.04 116.68,22.29 116.68,24.83 116.49,25.02 114.32,25.02 114.09,24.79 114.09,23.62 113.08,22.61 112.98,22.61
UNNAMED_7_CAP_I131_N1 on TOP: 97.63,26.23 97.63,28.39 97.75,28.51 100.17,28.51 100.29,28.39 100.29,26.48 100.04,26.23
UNNAMED_7_CAP_I131_N1 on BOTTOM: 96.23,28.13 96.23,26.86 96.86,26.23 101.18,26.23 101.44,26.48 101.44,32.83 100.93,33.34 100.93,34.23 101.44,34.74 101.44,36.52 101.31,36.64 99.28,36.64 99.15,36.52 99.15,31.05
UNNAMED_7_CAP_I138_N1 on BOTTOM (solid shape): 97.58,18.37 97.58,17.53 98.34,16.76 99.11,16.76 99.11,16 98.98,15.88 98.17,15.88 97.54,16.51 97.28,16.76 96.67,16.76 96.67,18.54 97.41,18.54
UNNAMED_7_CAP_I142_N1 on BOTTOM: 95.04,21.21 95.04,23.5 95.3,23.75 95.3,24.77 96.06,24.77 96.82,24 96.82,21.21 96.69,21.08 95.17,21.08
VL on TOP: 26,2.23 26,3.37 26.13,3.5 29.55,3.5 29.68,3.37 29.68,2.1 29.55,1.97 26.25,1.97
VL on BOTTOM: 101.69,35.25 101.69,36.52 101.82,36.64 102.96,36.64 103.21,36.39 103.21,35.25 103.09,35.12 101.82,35.12
VL on L5_PWR: 79.57,43.73 125.59,43.73 125.59,7.27 77.73,7.27 77.73,1.27 26.23,1.27 26.23,3.42 27.06,4.25 43.94,4.25 44.06,4.28 44.17,4.35 47.12,7.3 72.9,7.3 73.02,7.33 73.12,7.4 75.95,10.22 106.05,10.22 106.17,10.25 106.27,10.32 107.16,11.21 107.23,11.31 107.25,11.43 107.25,21.21 107.23,21.33 107.16,21.43 106.27,22.32 106.17,22.39 106.05,22.42 94.24,22.42 93.66,22.99 93.66,26.16 93.64,26.28 93.57,26.39 92.17,27.78 92.07,27.85 91.95,27.88 80.65,27.88 79.57,28.96
VLD on TOP: 56.9,31.11 56.9,24.51 60.58,24.51 60.58,31.11
VLD on BOTTOM: 36.83,35.26 36.83,34.19 37.01,34.01 38.73,34.01 38.91,33.83 38.91,32.23 42.98,32.23 43.18,32.44 43.18,35.25 43,35.43 37.01,35.43
VLD on BOTTOM: 18.03,38.99 18.03,36.58 18.29,36.32 20.07,36.32 20.32,36.58 20.32,38.99 19.94,39.37 18.41,39.37
VLD on L5_PWR: 1.27,43.73 63.18,43.73 63.18,24.9 62.61,24.32 53.22,24.32 52.64,24.9 52.64,27.94 52.62,28.06 52.55,28.16 51.53,29.18 51.43,29.25 51.31,29.27 29.6,29.27 28.64,30.23 28.64,32.89 28.61,33.01 28.55,33.12 26.77,34.9 26.66,34.96 26.54,34.99 1.27,34.99
VSUB on TOP: 30.91,6.6 30.78,6.48 29.38,6.48 29.26,6.6 29.26,9.02 29.53,9.29 30.8,9.29 30.91,9.19
VSUB on BOTTOM: 100.42,19.62 100.55,19.75 102.96,19.75 103.48,20.27 103.47,20.77 103.47,21.3 103.7,21.53 105.75,21.53 106.01,21.28 106.01,14.16 105.75,13.91 103.72,13.91 103.47,14.16 103.47,16.83 103.21,17.08 101.56,17.08 101.31,17.34 101.31,17.72 100.8,18.35 100.55,18.35 100.42,18.48
VSUB on L5_PWR: 94.24,21.78 105.91,21.78 106.62,21.08 106.62,11.56 105.91,10.86 75.82,10.86 75.7,10.83 75.59,10.77 72.77,7.94 46.99,7.94 46.87,7.91 46.77,7.84 43.81,4.89 29.85,4.89 28.64,6.1 28.64,9.9 32.52,13.78 56.01,13.78 56.13,13.8 56.23,13.87 57.66,15.3 92.58,15.3 92.7,15.33 92.81,15.4 93.57,16.16 93.64,16.26 93.66,16.38 93.66,21.2

Small or netless copper shapes (teardrops, artwork), in the pictures only: 3 on TOP, 3 on BOTTOM

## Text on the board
Ref Des/Assembly Bottom: A | C
Ref Des/Silkscreen Bottom: A | C | SECONDARY SIDE | 08-051354 REV C Z
Ref Des/Assembly Top: C | A
Ref Des/Silkscreen Top: 96 CONF | S1 SETUP | RPI CONF | S5 SETUP | RPI | CONF | A | C | ADDI9035-36 | PRIMARY SIDE | 08-051354 REV C Z | 96TOF CAMERA1
XSECTION_CHART: *  SURFACE - 0 MIL | * SOLDERMASK_TOP MASK - 0.8 MIL | L1 TOP CONDUCTOR - 2 MIL | *  DIELECTRIC - 4 MIL | L2 L2_GND PLANE - 1.3 MIL | L3 L3_SIG CONDUCTOR - 0.65 MIL | *  DIELECTRIC - 7.33 MIL | L4 L4_GND PLANE - 1.3 MIL | *  DIELECTRIC - 3 MIL | L5 L5_PWR PLANE - 1.3 MIL | *  DIELECTRIC - 11.64 MIL | L6 L6_PWR PLANE - 1.3 MIL | L7 L7_GND PLANE - 1.3 MIL | L8 L8_SIG CONDUCTOR - 0.65 MIL | L9 L9_GND PLANE - 1.3 MIL | L10 BOTTOM CONDUCTOR - 2 MIL | * SOLDERMASK_BOTTOM MASK - 0.8 MIL | DESIGN CROSS SECTION CHART | ___________________________ | TOTAL THICKNESS 63 MIL | 1-10 | 1-2 | 2-3
PAGE_OUTLINE: B | C | AS PER ECR-085792 & ECR-086716 | AS PER ECR-088820 | 20MAR19 | 16JUL19 | A.COZMA | MEZZANINE BOARD Z
DIMENSION: (REF) | DIA MAX | +2/-0 MILS
User.8: L2 GND | 08-      -07
User.9: L3 SIG | 08-      -08
User.11: L4 GND | 08-      -09
User.12: 16.    BOARDS TO BE PANELIZED AND SHIPPED INTACT. | IMPEDANCE CONTROLLED LINES = 0.004" ( L3 AND  L8) | CHARACTERISTIC IMPEDANCE = 50 OHMS +/- 10% | ARTWORK LINE WIDTH FOR | IMPEDANCE CONTROLLED LINES = 0.00525" ( L1 AND  L10) | IMPEDANCE CONTROLLED SPACE = 0.00525" | IMPEDANCE CONTROLLED SPACE = 0.008" | 0.00065" | 0.0013" | 0.002" | 0.004" | 0.00733" | 0.003" | 0.01164" | 50 OHMS, | 100 OHMS | 2
User.15: L5 PWR | 08-      -10
User.16: L6 PWR | 08-      -11
User.17: L7 GND | 08-      -12
User.18: L8 SIG | 08-      -13
User.19: L9 GND | 08-      -14
User.20: L11 GROUND
User.21: L10 SIGNAL
User.22: L12 SIGNAL
User.23: L13 GROUND
User.29: 3 | DRILLED HOLES LAYER 2 TO LAYER 3 | DIA MAX | SEE NOTE 15
User.30: 4 | DRILLED HOLES LAYER 2 TO LAYER 5 | DIA MAX
User.31: 5 | DRILLED HOLES LAYER 2 TO LAYER 11 | DIA MAX | SEE NOTE 15
User.32: SECONDARY SIDE
User.45: DRILLED HOLES LAYER 9 TO LAYER 10 | FIGURE | SIZE | 8.0 | 10.0 | 12.0 | 70.0 | 31.0 | 40.0 | 40.16 | 47.0 | 57.09 | 59.0 | 63.0 | 71.0 | 98.0 | 120.0 | 5.0 | TOLERANCE | +0.0/-0.0 | +1.97/-1.97 | +3.0/-3.0 | DRILL CHART: TOP to BOTTOM | FINISHED HOLES IN MILS | PLATED | NON-PLATED | DRILL CHART: TOP to L2_GND | DRILL CHART: L2_GND to L3_SIG | QTY | 19 | 317 | 227 | 3 | 1 | 2 | 4 | 73 | 35 | TOLERANCE/NOTES
